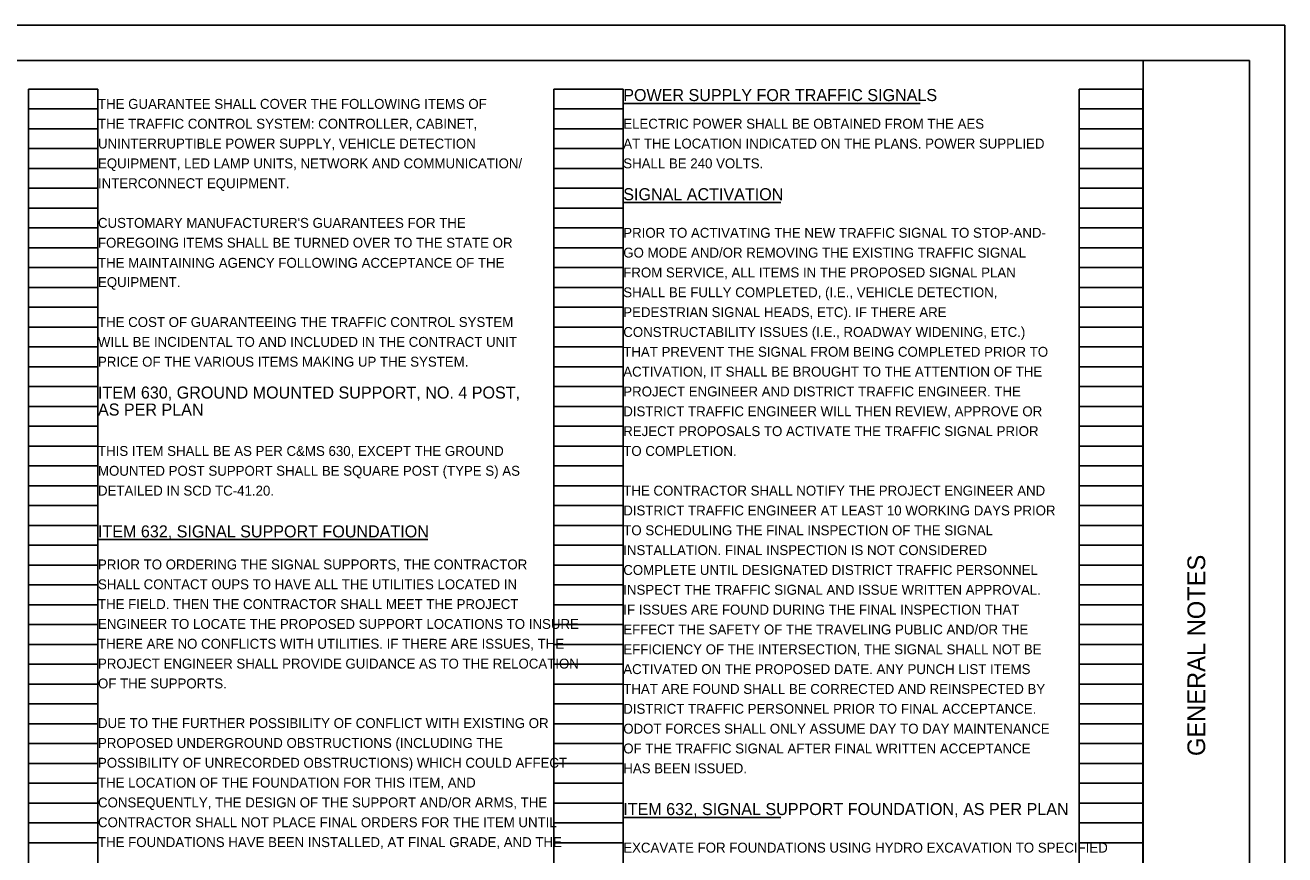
# Model space of a CAD drawing. Extents: x 0 to 34, y -1.2 to 22.
# Drawn here: x 16.21 to 34, y 10.33 to 22.04 of the extents above; entities that cross this region are included whole.
import ezdxf

# ---------------------------------------------------------------- set-up
doc = ezdxf.new("R2010")
doc.units = 0
for name, color, linetype in [('SH_Border', 7, 'Continuous'), ('SH_Cut_Line', 7, 'Continuous'), ('SH_Data', 7, 'Continuous'), ('SH_Text', 7, 'Continuous')]:
    doc.layers.add(name, color=color, linetype=linetype)

msp = doc.modelspace()

# ---------------------------------------------------------------- linework, layer by layer
at = {"layer": 'SH_Border'}
msp.add_line((32.005, 0.541), (32.005, 21.541), dxfattribs=at)
msp.add_lwpolyline([(1.505, 21.541), (33.505, 21.541), (33.505, 0.541), (1.505, 0.541)], close=True, dxfattribs=at)
at = {"layer": 'SH_Cut_Line'}
msp.add_lwpolyline([(0.005, 0.041), (34.005, 0.041), (34.005, 22.041), (0.005, 22.041)], close=True, dxfattribs=at)
at = {"layer": 'SH_Data'}
for p, q in [((16.26, 0.98), (16.26, 21.14)), ((16.26, 21.14), (17.24, 21.14)), ((17.24, 0.98), (17.24, 21.14)), ((23.68, 0.98), (23.68, 21.14)), ((23.68, 21.14), (24.66, 21.14)), ((24.66, 0.98), (24.66, 21.14)), ((31.1, 0.98), (31.1, 21.14)), ((31.1, 21.14), (32, 21.14)), ((32, 0.98), (32, 21.14)), ((16.26, 20.86), (17.24, 20.86)), ((23.68, 20.86), (24.66, 20.86)), ((31.1, 20.86), (32, 20.86)), ((16.26, 20.58), (17.24, 20.58)), ((23.68, 20.58), (24.66, 20.58)), ((31.1, 20.58), (32, 20.58)), ((16.26, 20.3), (17.24, 20.3)), ((23.68, 20.3), (24.66, 20.3)), ((31.1, 20.3), (32, 20.3)), ((16.26, 20.02), (17.24, 20.02)), ((23.68, 20.02), (24.66, 20.02)), ((31.1, 20.02), (32, 20.02)), ((16.26, 19.74), (17.24, 19.74)), ((23.68, 19.74), (24.66, 19.74)), ((31.1, 19.74), (32, 19.74)), ((16.26, 19.46), (17.24, 19.46)), ((23.68, 19.46), (24.66, 19.46)), ((31.1, 19.46), (32, 19.46)), ((16.26, 19.18), (17.24, 19.18)), ((23.68, 19.18), (24.66, 19.18)), ((31.1, 19.18), (32, 19.18)), ((16.26, 18.9), (17.24, 18.9)), ((23.68, 18.9), (24.66, 18.9)), ((31.1, 18.9), (32, 18.9)), ((16.26, 18.62), (17.24, 18.62)), ((23.68, 18.62), (24.66, 18.62)), ((31.1, 18.62), (32, 18.62)), ((16.26, 18.34), (17.24, 18.34)), ((23.68, 18.34), (24.66, 18.34)), ((31.1, 18.34), (32, 18.34)), ((16.26, 18.06), (17.24, 18.06)), ((23.68, 18.06), (24.66, 18.06)), ((31.1, 18.06), (32, 18.06)), ((16.26, 17.78), (17.24, 17.78)), ((23.68, 17.78), (24.66, 17.78)), ((31.1, 17.78), (32, 17.78)), ((16.26, 17.5), (17.24, 17.5)), ((23.68, 17.5), (24.66, 17.5)), ((31.1, 17.5), (32, 17.5)), ((16.26, 17.22), (17.24, 17.22)), ((23.68, 17.22), (24.66, 17.22)), ((31.1, 17.22), (32, 17.22)), ((16.26, 16.94), (17.24, 16.94)), ((23.68, 16.94), (24.66, 16.94)), ((31.1, 16.94), (32, 16.94)), ((16.26, 16.66), (17.24, 16.66)), ((23.68, 16.66), (24.66, 16.66)), ((31.1, 16.66), (32, 16.66)), ((16.26, 16.38), (17.24, 16.38)), ((23.68, 16.38), (24.66, 16.38)), ((31.1, 16.38), (32, 16.38)), ((16.26, 16.1), (17.24, 16.1)), ((23.68, 16.1), (24.66, 16.1)), ((31.1, 16.1), (32, 16.1)), ((16.26, 15.82), (17.24, 15.82)), ((23.68, 15.82), (24.66, 15.82)), ((31.1, 15.82), (32, 15.82)), ((16.26, 15.54), (17.24, 15.54)), ((23.68, 15.54), (24.66, 15.54)), ((31.1, 15.54), (32, 15.54)), ((16.26, 15.26), (17.24, 15.26)), ((23.68, 15.26), (24.66, 15.26)), ((31.1, 15.26), (32, 15.26)), ((16.26, 14.98), (17.24, 14.98)), ((23.68, 14.98), (24.66, 14.98)), ((31.1, 14.98), (32, 14.98)), ((16.26, 14.7), (17.24, 14.7)), ((23.68, 14.7), (24.66, 14.7)), ((31.1, 14.7), (32, 14.7)), ((16.26, 14.42), (17.24, 14.42)), ((23.68, 14.42), (24.66, 14.42)), ((31.1, 14.42), (32, 14.42)), ((16.26, 14.14), (17.24, 14.14)), ((23.68, 14.14), (24.66, 14.14)), ((31.1, 14.14), (32, 14.14)), ((16.26, 13.86), (17.24, 13.86)), ((23.68, 13.86), (24.66, 13.86)), ((31.1, 13.86), (32, 13.86)), ((16.26, 13.58), (17.24, 13.58)), ((23.68, 13.58), (24.66, 13.58)), ((31.1, 13.58), (32, 13.58)), ((16.26, 13.3), (17.24, 13.3)), ((23.68, 13.3), (24.66, 13.3)), ((31.1, 13.3), (32, 13.3)), ((16.26, 13.02), (17.24, 13.02)), ((23.68, 13.02), (24.66, 13.02)), ((31.1, 13.02), (32, 13.02)), ((16.26, 12.74), (17.24, 12.74)), ((23.68, 12.74), (24.66, 12.74)), ((31.1, 12.74), (32, 12.74)), ((16.26, 12.46), (17.24, 12.46)), ((23.68, 12.46), (24.66, 12.46)), ((31.1, 12.46), (32, 12.46)), ((16.26, 12.18), (17.24, 12.18)), ((23.68, 12.18), (24.66, 12.18)), ((31.1, 12.18), (32, 12.18)), ((16.26, 11.9), (17.24, 11.9)), ((23.68, 11.9), (24.66, 11.9)), ((31.1, 11.9), (32, 11.9)), ((16.26, 11.62), (17.24, 11.62)), ((23.68, 11.62), (24.66, 11.62)), ((31.1, 11.62), (32, 11.62)), ((16.26, 11.34), (17.24, 11.34)), ((23.68, 11.34), (24.66, 11.34)), ((31.1, 11.34), (32, 11.34)), ((16.26, 11.06), (17.24, 11.06)), ((23.68, 11.06), (24.66, 11.06)), ((31.1, 11.06), (32, 11.06)), ((16.26, 10.78), (17.24, 10.78)), ((23.68, 10.78), (24.66, 10.78)), ((31.1, 10.78), (32, 10.78)), ((16.26, 10.5), (17.24, 10.5)), ((23.68, 10.5), (24.66, 10.5)), ((31.1, 10.5), (32, 10.5))]:
    msp.add_line(p, q, dxfattribs=at)
at = {"layer": 'SH_Text'}
for p, q in [((24.66, 20.936), (28.856, 20.936)), ((24.66, 19.536), (26.886, 19.536)), ((17.24, 14.778), (21.901, 14.778)), ((24.66, 10.856), (26.886, 10.856))]:
    msp.add_line(p, q, dxfattribs=at)

# ---------------------------------------------------------------- texts
at = {"layer": 'SH_Data'}
msp.add_text('GENERAL NOTES', height=0.25, rotation=90, dxfattribs=at).set_placement((32.88, 11.723))
at = {"layer": 'SH_Text'}
for s, height, p in [('THE GUARANTEE SHALL COVER THE FOLLOWING ITEMS OF', 0.14, (17.24, 20.86)), ('POWER SUPPLY FOR TRAFFIC SIGNALS', 0.17, (24.66, 20.97)), ('THE TRAFFIC CONTROL SYSTEM: CONTROLLER, CABINET,', 0.14, (17.24, 20.58)), ('ELECTRIC POWER SHALL BE OBTAINED FROM THE AES', 0.14, (24.66, 20.58)), ('UNINTERRUPTIBLE POWER SUPPLY, VEHICLE DETECTION', 0.14, (17.24, 20.3)), ('AT THE LOCATION INDICATED ON THE PLANS. POWER SUPPLIED', 0.14, (24.66, 20.3)), ('EQUIPMENT, LED LAMP UNITS, NETWORK AND COMMUNICATION/', 0.14, (17.24, 20.02)), ('SHALL BE 240 VOLTS.', 0.14, (24.66, 20.02)), ('INTERCONNECT EQUIPMENT.', 0.14, (17.24, 19.74)), ('SIGNAL ACTIVATION', 0.17, (24.66, 19.57)), ("CUSTOMARY MANUFACTURER'S GUARANTEES FOR THE", 0.14, (17.24, 19.18)), ('FOREGOING ITEMS SHALL BE TURNED OVER TO THE STATE OR', 0.14, (17.24, 18.9)), ('PRIOR TO ACTIVATING THE NEW TRAFFIC SIGNAL TO STOP-AND-', 0.14, (24.66, 19.04)), ('GO MODE AND/OR REMOVING THE EXISTING TRAFFIC SIGNAL', 0.14, (24.66, 18.76)), ('THE MAINTAINING AGENCY FOLLOWING ACCEPTANCE OF THE', 0.14, (17.24, 18.616)), ('FROM SERVICE, ALL ITEMS IN THE PROPOSED SIGNAL PLAN', 0.14, (24.66, 18.48)), ('EQUIPMENT.', 0.14, (17.24, 18.344)), ('SHALL BE FULLY COMPLETED, (I.E., VEHICLE DETECTION,', 0.14, (24.66, 18.2)), ('PEDESTRIAN SIGNAL HEADS, ETC). IF THERE ARE', 0.14, (24.66, 17.92)), ('THE COST OF GUARANTEEING THE TRAFFIC CONTROL SYSTEM', 0.14, (17.24, 17.78)), ('WILL BE INCIDENTAL TO AND INCLUDED IN THE CONTRACT UNIT', 0.14, (17.24, 17.5)), ('CONSTRUCTABILITY ISSUES (I.E., ROADWAY WIDENING, ETC.)', 0.14, (24.66, 17.64)), ('THAT PREVENT THE SIGNAL FROM BEING COMPLETED PRIOR TO', 0.14, (24.66, 17.36)), ('PRICE OF THE VARIOUS ITEMS MAKING UP THE SYSTEM.', 0.14, (17.24, 17.22)), ('ACTIVATION, IT SHALL BE BROUGHT TO THE ATTENTION OF THE', 0.14, (24.66, 17.08)), ('ITEM 630, GROUND MOUNTED SUPPORT, NO. 4 POST, ', 0.17, (17.24, 16.77)), ('PROJECT ENGINEER AND DISTRICT TRAFFIC ENGINEER. THE', 0.14, (24.66, 16.8)), ('AS PER PLAN', 0.17, (17.24, 16.53)), ('DISTRICT TRAFFIC ENGINEER WILL THEN REVIEW, APPROVE OR', 0.14, (24.66, 16.52)), ('REJECT PROPOSALS TO ACTIVATE THE TRAFFIC SIGNAL PRIOR', 0.14, (24.66, 16.24)), ('THIS ITEM SHALL BE AS PER C&MS 630, EXCEPT THE GROUND ', 0.14, (17.24, 15.96)), ('TO COMPLETION.', 0.14, (24.66, 15.96)), ('MOUNTED POST SUPPORT SHALL BE SQUARE POST (TYPE S) AS ', 0.14, (17.24, 15.68)), ('DETAILED IN SCD TC-41.20.', 0.14, (17.24, 15.4)), ('THE CONTRACTOR SHALL NOTIFY THE PROJECT ENGINEER AND', 0.14, (24.66, 15.4)), ('DISTRICT TRAFFIC ENGINEER AT LEAST 10 WORKING DAYS PRIOR', 0.14, (24.66, 15.12)), ('ITEM 632, SIGNAL SUPPORT FOUNDATION', 0.17, (17.24, 14.81)), ('TO SCHEDULING THE FINAL INSPECTION OF THE SIGNAL', 0.14, (24.66, 14.84)), ('INSTALLATION. FINAL INSPECTION IS NOT CONSIDERED', 0.14, (24.66, 14.56)), ('PRIOR TO ORDERING THE SIGNAL SUPPORTS, THE CONTRACTOR', 0.14, (17.24, 14.358)), ('COMPLETE UNTIL DESIGNATED DISTRICT TRAFFIC PERSONNEL', 0.14, (24.66, 14.28)), ('SHALL CONTACT OUPS TO HAVE ALL THE UTILITIES LOCATED IN', 0.14, (17.24, 14.078)), ('INSPECT THE TRAFFIC SIGNAL AND ISSUE WRITTEN APPROVAL.', 0.14, (24.66, 14)), ('THE FIELD. THEN THE CONTRACTOR SHALL MEET THE PROJECT ', 0.14, (17.24, 13.798)), ('IF ISSUES ARE FOUND DURING THE FINAL INSPECTION THAT', 0.14, (24.66, 13.72)), ('ENGINEER TO LOCATE THE PROPOSED SUPPORT LOCATIONS TO INSURE ', 0.14, (17.24, 13.518)), ('EFFECT THE SAFETY OF THE TRAVELING PUBLIC AND/OR THE', 0.14, (24.66, 13.44)), ('THERE ARE NO CONFLICTS WITH UTILITIES. IF THERE ARE ISSUES, THE ', 0.14, (17.24, 13.238)), ('EFFICIENCY OF THE INTERSECTION, THE SIGNAL SHALL NOT BE', 0.14, (24.66, 13.16)), ('PROJECT ENGINEER SHALL PROVIDE GUIDANCE AS TO THE RELOCATION ', 0.14, (17.24, 12.958)), ('ACTIVATED ON THE PROPOSED DATE. ANY PUNCH LIST ITEMS', 0.14, (24.66, 12.88)), ('OF THE SUPPORTS.', 0.14, (17.24, 12.678)), ('THAT ARE FOUND SHALL BE CORRECTED AND REINSPECTED BY', 0.14, (24.66, 12.6)), ('DISTRICT TRAFFIC PERSONNEL PRIOR TO FINAL ACCEPTANCE.', 0.14, (24.66, 12.32)), ('DUE TO THE FURTHER POSSIBILITY OF CONFLICT WITH EXISTING OR ', 0.14, (17.24, 12.118)), ('ODOT FORCES SHALL ONLY ASSUME DAY TO DAY MAINTENANCE', 0.14, (24.66, 12.04)), ('PROPOSED UNDERGROUND OBSTRUCTIONS (INCLUDING THE ', 0.14, (17.24, 11.838)), ('OF THE TRAFFIC SIGNAL AFTER FINAL WRITTEN ACCEPTANCE', 0.14, (24.66, 11.76)), ('POSSIBILITY OF UNRECORDED OBSTRUCTIONS) WHICH COULD AFFECT ', 0.14, (17.24, 11.558)), ('HAS BEEN ISSUED.', 0.14, (24.66, 11.48)), ('THE LOCATION OF THE FOUNDATION FOR THIS ITEM, AND ', 0.14, (17.24, 11.278)), ('CONSEQUENTLY, THE DESIGN OF THE SUPPORT AND/OR ARMS, THE ', 0.14, (17.24, 10.998)), ('ITEM 632, SIGNAL SUPPORT FOUNDATION, AS PER PLAN', 0.17, (24.66, 10.89)), ('CONTRACTOR SHALL NOT PLACE FINAL ORDERS FOR THE ITEM UNTIL ', 0.14, (17.24, 10.718)), ('THE FOUNDATIONS HAVE BEEN INSTALLED, AT FINAL GRADE, AND THE ', 0.14, (17.24, 10.438)), ('EXCAVATE FOR FOUNDATIONS USING HYDRO EXCAVATION TO SPECIFIED ', 0.14, (24.66, 10.36))]:
    msp.add_text(s, height=height, dxfattribs=at).set_placement(p)

doc.saveas('drawing.dxf')
